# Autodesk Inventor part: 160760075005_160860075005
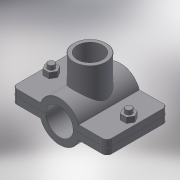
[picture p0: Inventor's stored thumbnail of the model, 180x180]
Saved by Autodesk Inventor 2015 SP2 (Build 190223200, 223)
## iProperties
Created: 2017-05
Part Number: 160760075005_160860075005
Material: Generic
Description: PLASSON SADDLE 75-1/2"
Document SubType Name: Modeling
Designer: KIM
Density: 1 g/cm^3
Appearance: Default
Author: KIM
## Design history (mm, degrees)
derived "16076.ipt"
feature "Solid1::16076.ipt"
feature "Solid2::16076.ipt"
tag "TaggingFeature1"
body "Solid1"
other parameters: "d0" = 93.75, "d1" = 122, "d2" = 37.5, "d3" = 75, "d4" = 98, "d5" = 0, "d6" = 6.1, "d7" = 122, "d8" = 0.1, "d10" = 0, "d11" = 0.75, "d14" = 24.2203, "d20" = 0.75, "d23" = 0.75, "d37" = 8, "d38" = 45.5, "d39" = 0, "d40" = 3, "d41" = 5, "d42" = 0, "d43" = 6, "d44" = 3, "d45" = 0, "d46" = 0.75, "d51" = 64, "d52" = 18.631, "d53" = 18, "d54" = 0, "d55" = 16, "d57" = 0, "d58" = 81, "d60" = 0, "d63" = 8, "d66" = 82, "d_" = 75, "B_" = 16, "G_" = 18.631, "A_" = 64, "L_" = 122, "L_1" = 98, "l_2" = 18
